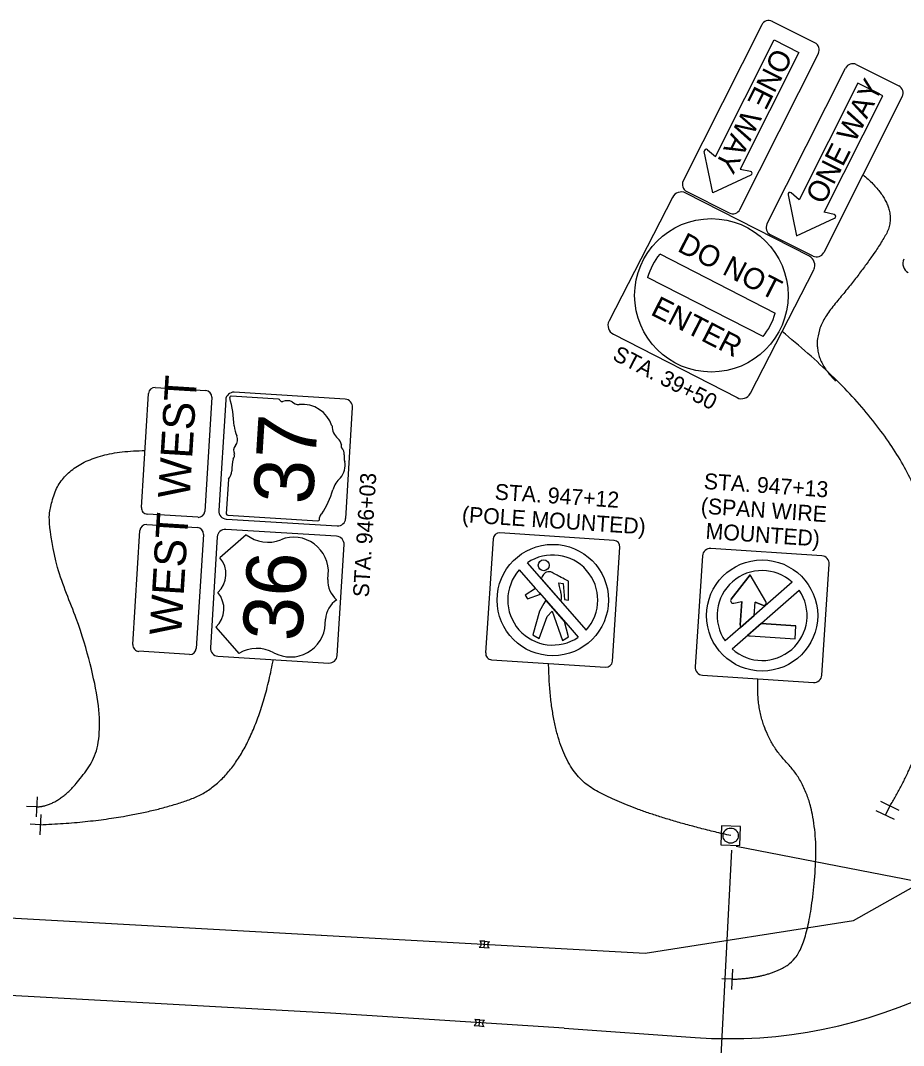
# Model space of a CAD drawing. Extents: x 1847379 to 1850904, y 217032 to 220169.
# Drawn here: x 1848740.8 to 1848879.8, y 218877.1 to 219038.5 of the extents above; entities that cross this region are included whole.
import ezdxf

# ---------------------------------------------------------------- set-up
doc = ezdxf.new("R2010")
doc.units = 0
for name, color, linetype in [('PM_P_Cells', 7, 'Continuous'), ('PM_P_Dotted_Line', 7, 'Continuous'), ('PM_P_Edge_Line', 7, 'Continuous'), ('PM_P_Lane_Line', 7, 'Continuous'), ('SG_X_Wiring', 7, 'Continuous'), ('SN_X_Foundation', 7, 'Continuous'), ('SN_X_Public', 7, 'Continuous'), ('SN_X_Text', 7, 'Continuous')]:
    doc.layers.add(name, color=color, linetype=linetype)

msp = doc.modelspace()

# ---------------------------------------------------------------- linework, layer by layer
at = {"layer": 'PM_P_Cells'}
for p, q in [((1848813.03, 218892.56), (1848813.8, 218892.49)), ((1848813.03, 218892.56), (1848813.8, 218892.49)), ((1848813.89, 218893.46), (1848813.12, 218893.53)), ((1848813.12, 218893.53), (1848813.89, 218893.46)), ((1848813.8, 218892.49), (1848813.89, 218893.46)), ((1848813.8, 218892.49), (1848814.57, 218892.42)), ((1848813.89, 218893.46), (1848814.66, 218893.39)), ((1848813.09, 218881.1), (1848812.32, 218881.17)), ((1848812.32, 218881.17), (1848813.09, 218881.1)), ((1848813, 218880.13), (1848813.09, 218881.1)), ((1848813.09, 218881.1), (1848813.85, 218881.04)), ((1848812.23, 218880.2), (1848813, 218880.13)), ((1848812.23, 218880.2), (1848813, 218880.13)), ((1848813, 218880.13), (1848813.77, 218880.06))]:
    msp.add_line(p, q, dxfattribs=at)
for centre, start, end in [((1848812.77, 218893.07), 296.8063, 52.8586), ((1848812.77, 218893.07), 296.8063, 52.8586), ((1848814.92, 218892.88), 116.8063, 232.8586), ((1848811.97, 218880.72), 296.8063, 52.8586), ((1848811.97, 218880.72), 296.8063, 52.8586), ((1848814.11, 218880.52), 116.8063, 232.8586)]:
    msp.add_arc(centre, 0.576, start, end, dxfattribs=at)
at = {"layer": 'PM_P_Dotted_Line'}
msp.add_line((1848826.4, 218879.79), (1848847, 218878.32), dxfattribs=at)
msp.add_arc((1848852.35, 218953.13), 75, 265.9117, 327.3396, dxfattribs=at)
at = {"layer": 'PM_P_Edge_Line'}
for p, q in [((1848468.87, 218912.17), (1848839.16, 218891.61)), ((1848871.96, 218896.75), (1848890.9, 218907.47)), ((1848839.16, 218891.61), (1848871.96, 218896.75))]:
    msp.add_line(p, q, dxfattribs=at)
at = {"layer": 'PM_P_Lane_Line'}
msp.add_lwpolyline([(1848093.91, 218917.13), (1848143.09, 218915.12), (1848190.28, 218912.91), (1848241.04, 218910.6), (1848292.87, 218908.29), (1848342.88, 218905.97), (1848396.54, 218903.43), (1848443.56, 218901.44), (1848492.82, 218898.95), (1848543.12, 218896.17), (1848588.69, 218893.34), (1848639.37, 218890.51), (1848690.94, 218887.73), (1848738.16, 218885.02), (1848789.62, 218882.19), (1848826.41, 218879.84)], dxfattribs=at)
at = {"layer": 'SG_X_Wiring'}
for p, q in [((1848954.76, 218888.78), (1848853.47, 218908.37)), ((1848847.49, 218805.29), (1848852.77, 218907.83))]:
    msp.add_line(p, q, dxfattribs=at)
at = {"layer": 'SN_X_Foundation'}
msp.add_lwpolyline([(1848854.05, 218908.55), (1848854.16, 218911.55), (1848851.16, 218911.65), (1848851.05, 218908.66)], close=True, dxfattribs=at)
msp.add_circle((1848852.61, 218910.1), 1.2, dxfattribs=at)
at = {"layer": 'SN_X_Public'}
for p, q in [((1848850.21, 219017.03), (1848859.45, 219035.39)), ((1848859.45, 219035.39), (1848863.36, 219033.42)), ((1848863.36, 219033.42), (1848854.11, 219015.06)), ((1848872.65, 219028.59), (1848863.4, 219010.23)), ((1848876.55, 219026.62), (1848872.65, 219028.59)), ((1848867.31, 219008.26), (1848876.55, 219026.62)), ((1848848.97, 219018.11), (1848850.21, 219017.03)), ((1848849.78, 219011.33), (1848848.46, 219017.81)), ((1848854.11, 219015.06), (1848855.73, 219014.71)), ((1848855.79, 219014.12), (1848849.78, 219011.33)), ((1848861.64, 219011.02), (1848862.98, 219004.53)), ((1848863.4, 219010.23), (1848862.16, 219011.32)), ((1848862.98, 219004.53), (1848868.98, 219007.32)), ((1848868.91, 219007.91), (1848867.31, 219008.26)), ((1848841.44, 219001.69), (1848859.61, 218992.39)), ((1848857.71, 218988.68), (1848839.54, 218997.98)), ((1848759.82, 218961.78), (1848760.93, 218979.74)), ((1848761.99, 218980.68), (1848769.97, 218980.19)), ((1848770.91, 218979.13), (1848769.8, 218961.16)), ((1848781.41, 218978.84), (1848773.98, 218979.3)), ((1848781.41, 218978.84), (1848781.41, 218978.84)), ((1848773.53, 218966.23), (1848773.19, 218960.75)), ((1848768.74, 218960.23), (1848760.76, 218960.72)), ((1848773.43, 218960.55), (1848787.63, 218959.67)), ((1848760.66, 218959.09), (1848768.64, 218958.6)), ((1848758.49, 218940.19), (1848759.6, 218958.15)), ((1848769.58, 218957.54), (1848768.47, 218939.57)), ((1848776.33, 218957.49), (1848772.19, 218953.84)), ((1848820.59, 218953.05), (1848829.87, 218942.46)), ((1848789.2, 218950.44), (1848789.25, 218951.22)), ((1848822.78, 218950.56), (1848822.88, 218950.45)), ((1848822.88, 218950.45), (1848825.88, 218947.02)), ((1848852.69, 218947.35), (1848855.69, 218951.15)), ((1848858.16, 218946.99), (1848855.69, 218951.15)), ((1848821.88, 218949.03), (1848820.27, 218947.98)), ((1848821.88, 218949.03), (1848820.27, 218947.98)), ((1848825.54, 218949.9), (1848826.26, 218949.82)), ((1848825.54, 218949.9), (1848826.26, 218949.82)), ((1848826.26, 218949.82), (1848826.46, 218947.27)), ((1848826.26, 218949.82), (1848826.46, 218947.27)), ((1848827.07, 218950.17), (1848827.05, 218950.17)), ((1848827.07, 218950.17), (1848827.05, 218950.17)), ((1848827.1, 218947.17), (1848827.07, 218950.17)), ((1848827.1, 218947.17), (1848827.07, 218950.17)), ((1848852.82, 218939.5), (1848863.4, 218948.77)), ((1848820.27, 218947.98), (1848820.63, 218947.37)), ((1848820.27, 218947.98), (1848820.63, 218947.37)), ((1848820.63, 218947.37), (1848822.65, 218948.15)), ((1848820.63, 218947.37), (1848822.65, 218948.15)), ((1848822.65, 218948.15), (1848822.5, 218948.33)), ((1848823.51, 218947.17), (1848823.21, 218946.68)), ((1848823.51, 218947.17), (1848823.21, 218946.68)), ((1848823.56, 218947.11), (1848823.51, 218947.17)), ((1848826.44, 218943.83), (1848823.56, 218947.11)), ((1848826.46, 218947.27), (1848827.1, 218947.17)), ((1848826.46, 218947.27), (1848827.1, 218947.17)), ((1848823.21, 218946.68), (1848822.52, 218945.44)), ((1848823.21, 218946.68), (1848822.52, 218945.44)), ((1848853.12, 218946.69), (1848854.37, 218946.99)), ((1848854.13, 218943.32), (1848854.37, 218946.99)), ((1848856.31, 218944.77), (1848856.45, 218946.86)), ((1848857.65, 218946.39), (1848856.45, 218946.86)), ((1848788.77, 218943.42), (1848788.82, 218944.2)), ((1848822.52, 218945.44), (1848821.45, 218941.72)), ((1848822.52, 218945.44), (1848821.45, 218941.72)), ((1848822.44, 218941.15), (1848823.71, 218944.6)), ((1848822.44, 218941.15), (1848823.71, 218944.6)), ((1848823.71, 218944.6), (1848824.49, 218945.45)), ((1848823.71, 218944.6), (1848824.49, 218945.45)), ((1848824.49, 218945.45), (1848826.15, 218940.82)), ((1848824.49, 218945.45), (1848826.15, 218940.82)), ((1848771.52, 218942.92), (1848775.18, 218938.78)), ((1848827.08, 218941.43), (1848826.44, 218943.83)), ((1848827.08, 218941.43), (1848826.44, 218943.83)), ((1848857.41, 218943.52), (1848862.89, 218943.16)), ((1848862.75, 218941.08), (1848862.89, 218943.16)), ((1848821.45, 218941.72), (1848822.44, 218941.15)), ((1848821.45, 218941.72), (1848822.44, 218941.15)), ((1848826.15, 218940.82), (1848827.08, 218941.43)), ((1848826.15, 218940.82), (1848827.08, 218941.43)), ((1848855.68, 218941.54), (1848862.75, 218941.08)), ((1848767.41, 218938.63), (1848759.42, 218939.13)), ((1848743.41, 218916.23), (1848743.25, 218913.04)), ((1848879.12, 218914.07), (1848876.24, 218915.46)), ((1848743.33, 218914.63), (1848741.73, 218914.71)), ((1848743.98, 218913.42), (1848743.82, 218910.22)), ((1848878.42, 218912.63), (1848875.54, 218914.02)), ((1848876.98, 218913.32), (1848877.68, 218914.76)), ((1848877.33, 218914.04), (1848877.33, 218914.04)), ((1848743.9, 218911.82), (1848742.3, 218911.9)), ((1848852.88, 218889.08), (1848852.73, 218885.89)), ((1848852.81, 218887.48), (1848851.21, 218887.56))]:
    msp.add_line(p, q, dxfattribs=at)
for points in [[(1848857.5, 219037.77), (1848845.14, 219013.2)], [(1848865.87, 219034.95), (1848859.17, 219038.32)], [(1848854.07, 219008.71), (1848866.43, 219033.28)], [(1848872.38, 219031.53), (1848879.07, 219028.15)], [(1848858.33, 219006.41), (1848870.7, 219030.97)], [(1848879.63, 219026.47), (1848867.26, 219001.91)], [(1848843.43, 219010.61), (1848833.46, 218991.14)], [(1848865.01, 219001.33), (1848845.53, 219011.29)], [(1848845.69, 219011.53), (1848852.39, 219008.16)], [(1848865.58, 219001.36), (1848858.88, 219004.73)], [(1848855.72, 218979.75), (1848865.68, 218999.22)], [(1848834.14, 218989.04), (1848853.62, 218979.07)], [(1848791.9, 218978.84), (1848774.43, 218979.91)], [(1848773.1, 218978.74), (1848772.03, 218961.28)], [(1848791.99, 218960.04), (1848793.07, 218977.51)], [(1848773.2, 218959.95), (1848790.66, 218958.87)], [(1848771.77, 218957.15), (1848770.69, 218939.68)], [(1848790.56, 218957.24), (1848773.1, 218958.32)], [(1848815.21, 218956.83), (1848814.03, 218938.87)], [(1848834.24, 218956.58), (1848816.28, 218957.76)], [(1848790.66, 218938.45), (1848791.73, 218955.92)], [(1848833.99, 218937.55), (1848835.17, 218955.51)], [(1848866.95, 218954.16), (1848849.49, 218955.31)], [(1848848.16, 218954.15), (1848847.01, 218936.69)], [(1848819.32, 218951.94), (1848821.85, 218949.06), (1848822.5, 218948.33), (1848822.5, 218948.33)], [(1848866.97, 218935.37), (1848868.12, 218952.83)], [(1848822.88, 218950.45), (1848822.88, 218950.45)], [(1848858.16, 218946.99), (1848855.69, 218951.15), (1848852.69, 218947.35)], [(1848822.5, 218948.33), (1848821.88, 218949.03), (1848821.88, 218949.03)], [(1848862.3, 218950.02), (1848856.31, 218944.77), (1848854.16, 218942.88)], [(1848822.5, 218948.33), (1848823.56, 218947.11), (1848827.02, 218943.17), (1848828.61, 218941.36)], [(1848853.12, 218946.69), (1848854.37, 218946.99), (1848854.13, 218943.32)], [(1848854.16, 218942.88), (1848856.31, 218944.77), (1848856.45, 218946.86), (1848857.65, 218946.39)], [(1848854.16, 218942.88), (1848851.72, 218940.75)], [(1848857.41, 218943.52), (1848855.25, 218941.63)], [(1848855.68, 218941.54), (1848862.75, 218941.08), (1848862.89, 218943.16), (1848857.41, 218943.52)], [(1848771.86, 218938.36), (1848789.33, 218937.28)], [(1848814.96, 218937.8), (1848832.92, 218936.62)], [(1848848.17, 218935.36), (1848865.64, 218934.21)]]:
    msp.add_lwpolyline(points, dxfattribs=at)
for centre, radius in [((1848849.57, 218995.18), 12.08), ((1848824.6, 218947.2), 8.77), ((1848823.18, 218952.68), 0.864), ((1848857.56, 218944.76), 8.75)]:
    msp.add_circle(centre, radius, dxfattribs=at)
for centre, radius, start, end in [((1848858.61, 219037.21), 1.25, 63.2883, 153.2883), ((1848865.31, 219033.84), 1.25, 333.2883, 63.2883), ((1848871.81, 219030.41), 1.25, 63.2655, 153.2655), ((1848878.51, 219027.04), 1.25, 333.2655, 63.2655), ((1848848.76, 219017.87), 0.314, 49.0451, 191.6608), ((1848855.66, 219014.4), 0.314, 294.9462, 77.5057), ((1848846.25, 219012.64), 1.25, 153.2883, 243.2883), ((1848844.82, 219009.9), 1.56, 62.9001, 152.9001), ((1848861.95, 219011.08), 0.314, 49.0481, 191.6075), ((1848852.95, 219009.27), 1.25, 243.2883, 333.2883), ((1848868.85, 219007.61), 0.314, 294.8929, 77.5087), ((1848859.44, 219005.85), 1.25, 153.2655, 243.2655), ((1848849.57, 218995.18), 10.42, 141.3632, 164.4371), ((1848864.29, 218999.94), 1.56, 332.9001, 62.9001), ((1848866.14, 219002.48), 1.25, 243.2655, 333.2655), ((1848881.28, 219000.18), 1.56, 153.1962, 243.1962), ((1848849.57, 218995.18), 10.42, 321.3632, 344.4371), ((1848834.85, 218990.43), 1.56, 152.9001, 242.9001), ((1848761.93, 218979.68), 1, 86.4679, 176.4679), ((1848769.91, 218979.19), 1, 356.4679, 86.4679), ((1848774.35, 218978.67), 1.25, 86.4679, 176.4679), ((1848854.33, 218980.46), 1.56, 242.9001, 332.9001), ((1848773.94, 218979.09), 0.209, 78.33, 184.2059), ((1848754.56, 218973.81), 19.88, 2.3124, 15.3744), ((1848781.43, 218978.62), 0.223, 16.0717, 94.202), ((1848781.96, 218978.76), 0.323, 194.4119, 296.8049), ((1848782.77, 218976.65), 1.94, 66.5009, 110.1175), ((1848784.57, 218979.4), 1.41, 223.2744, 273.3975), ((1848785.13, 218973.04), 4.97, 18.7768, 95.4538), ((1848791.82, 218977.59), 1.25, 356.4679, 86.4679), ((1848778.42, 218974.88), 4, 183.8141, 207.2368), ((1848792.56, 218974.68), 2.72, 180.871, 229.0447), ((1848773.45, 218972.49), 1.52, 320.3241, 21.2961), ((1848775.6, 218970.73), 1.26, 140.9346, 205.609), ((1848789.73, 218971.4), 1.61, 9.3411, 49.745), ((1848791.7, 218971.46), 0.428, 152.2196, 219.1163), ((1848773.9, 218969.94), 0.608, 306.26, 23.5703), ((1848790.24, 218970.17), 1.52, 355.2449, 42.0172), ((1848794.07, 218969.73), 2.34, 172.163, 197.6779), ((1848781.63, 218967.74), 7.56, 166.9546, 181.4562), ((1848789.06, 218968.38), 2.85, 317.1683, 12.7598), ((1848771.96, 218967.64), 2.11, 318.0874, 357.5798), ((1848794.25, 218963.2), 4.49, 133.6521, 162.3039), ((1848776.19, 218968.6), 14.36, 326.8808, 343.6664), ((1848760.82, 218961.72), 1, 176.4679, 266.4679), ((1848768.8, 218961.22), 1, 266.4679, 356.4679), ((1848773.27, 218961.2), 1.25, 176.4679, 266.4679), ((1848773.41, 218960.77), 0.217, 184.598, 274.598), ((1848788.49, 218960.21), 0.603, 116.2163, 179.7397), ((1848786.22, 218960.01), 1.67, 353.8069, 7.0718), ((1848790.74, 218960.12), 1.25, 266.4679, 356.4679), ((1848760.6, 218958.09), 1, 86.4679, 176.4679), ((1848768.58, 218957.6), 1, 356.4679, 86.4679), ((1848787.67, 218959.89), 0.219, 258.4263, 344.7745), ((1848773.02, 218957.07), 1.25, 86.4679, 176.4679), ((1848779.74, 218961.77), 5.47, 231.467, 291.9208), ((1848783.8, 218951.62), 5.47, 355.8297, 111.636), ((1848790.49, 218955.99), 1.25, 356.4679, 86.4679), ((1848816.21, 218956.76), 1, 86.2275, 176.2275), ((1848834.17, 218955.58), 1, 356.2275, 86.2275), ((1848849.41, 218954.07), 1.25, 86.2275, 176.2275), ((1848769.24, 218951.28), 3.91, 312.0409, 40.8949), ((1848824.6, 218947.2), 7.09, 318.0466, 124.3989), ((1848866.87, 218952.92), 1.25, 356.2275, 86.2275), ((1848824.6, 218947.2), 7.09, 138.0755, 304.4755), ((1848824.6, 218947.2), 7.09, 138.0755, 304.4755), ((1848793.1, 218950.2), 3.91, 176.4679, 229.598), ((1848857.56, 218944.76), 7.08, 47.9839, 214.4712), ((1848857.56, 218944.76), 7.08, 47.9839, 214.4712), ((1848857.56, 218944.76), 7.08, 227.9839, 34.4712), ((1848768.9, 218945.82), 3.91, 312.0409, 40.8949), ((1848792.72, 218943.96), 3.91, 123.3378, 176.4679), ((1848853.02, 218947.1), 0.417, 141.7113, 283.5894), ((1848853.02, 218947.1), 0.417, 141.7113, 283.5894), ((1848857.8, 218946.78), 0.417, 248.8657, 30.7438), ((1848857.8, 218946.78), 0.417, 248.8657, 30.7438), ((1848783.31, 218943.7), 5.47, 241.2998, 357.1062), ((1848855.79, 218943.21), 1.67, 176.2275, 191.2275), ((1848855.79, 218943.21), 1.67, 176.2275, 191.2275), ((1848855.79, 218943.21), 1.67, 251.2275, 266.2275), ((1848855.79, 218943.21), 1.67, 251.2275, 266.2275), ((1848759.49, 218940.12), 1, 176.4679, 266.4679), ((1848767.47, 218939.63), 1, 266.4679, 356.4679), ((1848771.94, 218939.61), 1.25, 176.4679, 266.4679), ((1848778.03, 218934.12), 5.47, 61.015, 121.4688), ((1848789.41, 218938.53), 1.25, 266.4679, 356.4679), ((1848815.03, 218938.8), 1, 176.2275, 266.2275), ((1848832.99, 218937.62), 1, 266.2275, 356.2275), ((1848848.26, 218936.61), 1.25, 176.2275, 266.2275), ((1848865.72, 218935.45), 1.25, 266.2275, 356.2275)]:
    msp.add_arc(centre, radius, start, end, dxfattribs=at)
for points, degree in [([(1848873.44, 219014.19), (1848879.59, 219008.99), (1848874.24, 219000.01), (1848863.47, 218987.19), (1848869.14, 218981.69)], 2), ([(1848877.68, 218914.76), (1848882.95, 218923.3), (1848886.59, 218944.99), (1848880.24, 218973.57), (1848860.7, 218989.49)], 2), ([(1848743.33, 218914.63), (1848747.61, 218914.75), (1848756.02, 218928.02), (1848739.42, 218970.46), (1848760.38, 218970.76)], 2), ([(1848827.05, 218950.17), (1848826.19, 218950.62), (1848824.85, 218951.34), (1848824.36, 218951.61), (1848824.19, 218951.65), (1848824.02, 218951.66), (1848823.62, 218951.69), (1848823.09, 218951.25), (1848822.9, 218950.82), (1848822.78, 218950.56)], 3), ([(1848827.05, 218950.17), (1848826.19, 218950.62), (1848824.85, 218951.34), (1848824.36, 218951.61), (1848824.19, 218951.65), (1848824.02, 218951.66), (1848823.62, 218951.69), (1848823.09, 218951.25), (1848822.9, 218950.82), (1848822.78, 218950.56)], 3), ([(1848825.88, 218947.02), (1848825.91, 218947.09), (1848825.99, 218947.29), (1848825.99, 218947.75), (1848825.93, 218948.17), (1848825.78, 218948.9), (1848825.66, 218949.42), (1848825.54, 218949.9)], 3), ([(1848825.88, 218947.02), (1848825.91, 218947.09), (1848825.99, 218947.29), (1848825.99, 218947.75), (1848825.93, 218948.17), (1848825.78, 218948.9), (1848825.66, 218949.42), (1848825.54, 218949.9)], 3), ([(1848743.9, 218911.82), (1848757.92, 218912.39), (1848777.07, 218919.23), (1848780.6, 218937.82)], 2), ([(1848852.61, 218910.1), (1848837.46, 218913.57), (1848824.25, 218921.48), (1848823.94, 218937.21)], 2), ([(1848852.81, 218887.48), (1848859.19, 218887.73), (1848865.04, 218892.54), (1848866.76, 218916.06), (1848856.41, 218926.8), (1848856.91, 218934.78)], 2)]:
    msp.add_open_spline(points, degree=degree, dxfattribs=at)

# ---------------------------------------------------------------- texts
for s, height, rotation, p in [('ONE WAY', 3.333, 243.2883, (1848859.5, 219034.34)), ('ONE WAY', 3.333, 63.2655, (1848867.25, 219009.32)), ('DO NOT', 3.333, 332.9001, (1848844.06, 219002.21)), ('ENTER', 3.333, 332.9001, (1848839.84, 218992.21)), ('STA. 39+50', 2.5, 332.9001, (1848833.83, 218985.13)), ('WEST', 5, 86.4679, (1848767.42, 218963.1)), ('37', 9.375, 86.4679, (1848786.78, 218962.13)), ('STA. 946+03', 2.5, 86.4679, (1848795.62, 218947.58)), ('WEST', 5, 86.4679, (1848766.08, 218941.51)), ('36', 9.375, 86.4679, (1848785.07, 218940.56))]:
    msp.add_text(s, height=height, rotation=rotation, dxfattribs=at).set_placement(p)
at = {"layer": 'SN_X_Text'}
for s, rotation, p in [('STA. 947+13', 356.0516, (1848848.33, 218964.7)), ('STA. 947+12', 356.1465, (1848815.4, 218963.03)), ('(SPAN WIRE ', 356.0516, (1848847.85, 218960.82)), ('(POLE MOUNTED)', 356.1465, (1848810.24, 218959.47)), ('MOUNTED)', 356.0516, (1848848.6, 218956.86))]:
    msp.add_text(s, height=2.5, rotation=rotation, dxfattribs=at).set_placement(p)

doc.saveas('drawing.dxf')
